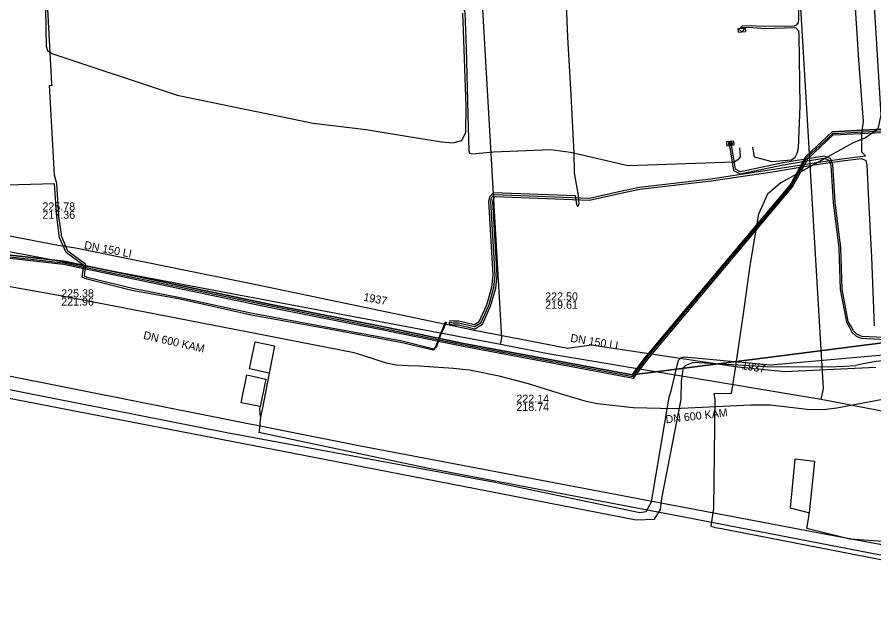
# Model space of a CAD drawing. Extents: x -599951 to -598963, y -1164095 to -1162939.
# Drawn here: x -599368.2 to -599282.6, y -1163169.1 to -1163110 of the extents above; entities that cross this region are included whole.
import ezdxf

# ---------------------------------------------------------------- set-up
doc = ezdxf.new("R2010")
doc.units = 0
for name, color, linetype in [('28', 7, 'Continuous'), ('31', 7, 'Continuous'), ('Vrstva 12', 7, 'Continuous'), ('Vrstva 13', 7, 'Continuous'), ('Vrstva 15', 7, 'Continuous'), ('Vrstva 19', 7, 'Continuous'), ('Vrstva 32', 7, 'Continuous'), ('Vrstva 42', 7, 'Continuous'), ('Vrstva 43', 7, 'Continuous'), ('Vrstva 44', 7, 'Continuous'), ('Vrstva 55', 7, 'Continuous'), ('Vrstva 58', 7, 'Continuous')]:
    doc.layers.add(name, color=color, linetype=linetype)

# ---------------------------------------------------------------- blocks, each defined once
blk = doc.blocks.new('NN630')
at = {"layer": '31'}
for points in [[(-0.003, -0.7), (-0.703, 0)], [(-0.703, -0.7), (-0.703, 0), (0.697, 0), (0.697, -0.7)], [(-0.003, -0.7), (0.697, 0)], [(-0.703, -0.7), (0.697, -0.7)]]:
    blk.add_lwpolyline(points, dxfattribs=at)
blk = doc.blocks.new('NN620')
at = {"layer": '28'}
for points in [[(0.752, 0.004), (-0.748, 0.004)], [(-0.748, 0.004), (-0.748, -0.746)], [(0.752, -0.746), (0.752, 0.004)], [(-0.748, -0.746), (0.752, -0.746)], [(0.368, -0.18), (-0.376, -0.18)], [(-0.376, -0.18), (-0.376, -0.558)], [(-0.376, -0.558), (0.368, -0.558)], [(0.321, -0.227), (-0.329, -0.227)], [(-0.329, -0.227), (-0.329, -0.51)], [(-0.329, -0.51), (0.321, -0.51)], [(0.274, -0.274), (-0.281, -0.274)], [(-0.281, -0.274), (-0.281, -0.463)], [(-0.281, -0.463), (0.274, -0.463)], [(0.227, -0.321), (-0.234, -0.321)], [(-0.234, -0.321), (-0.234, -0.416)], [(-0.234, -0.416), (0.227, -0.416)], [(-0.193, -0.369), (0.185, -0.369)], [(0.227, -0.416), (0.227, -0.321)], [(0.274, -0.463), (0.274, -0.274)], [(0.321, -0.51), (0.321, -0.227)], [(0.368, -0.558), (0.368, -0.18)]]:
    blk.add_lwpolyline(points, dxfattribs=at)

msp = doc.modelspace()

# ---------------------------------------------------------------- linework, layer by layer
at = {"layer": 'Vrstva 13'}
for p, q in [((-599370.101, -1163133.236), (-599319.892, -1163142.727)), ((-599319.892, -1163142.727), (-599319.824, -1163142.407)), ((-599287.815, -1163148.211), (-599287.66, -1163147.47)), ((-599287.815, -1163148.211), (-599286.249, -1163148.514)), ((-599286.249, -1163148.514), (-599280.123, -1163149.708))]:
    msp.add_line(p, q, dxfattribs=at)
for points in [[(-599287.66, -1163147.47), (-599287.596, -1163147.153), (-599291.469, -1163082.154), (-599292.48, -1163063.001), (-599295.243, -1163012.163), (-599300.148, -1162987.801), (-599300.278, -1162987.115), (-599302.071, -1162951.135)], [(-599319.824, -1163142.407), (-599319.759, -1163142.094), (-599323.979, -1163068.87), (-599326.68, -1163013.53)], [(-599319.892, -1163142.727), (-599314.969, -1163143.684), (-599287.815, -1163148.211)]]:
    msp.add_lwpolyline(points, dxfattribs=at)
at = {"layer": 'Vrstva 19'}
msp.add_lwpolyline([(-599283.03, -1163098.11), (-599283, -1163099.78), (-599282.98, -1163100.28), (-599282.759, -1163104.88), (-599282.75, -1163105.07), (-599281.86, -1163119.78), (-599282.17, -1163121.21), (-599283.38, -1163122.06), (-599284.63, -1163122.58), (-599291.87, -1163126.57), (-599293.2, -1163127.71), (-599294.09, -1163129.72), (-599294.97, -1163134.86), (-599295.61, -1163139.68), (-599296.53, -1163145.79), (-599296.83, -1163147.64), (-599298.55, -1163147.69), (-599298.47, -1163148.23), (-599298.58, -1163159.15), (-599298.84, -1163160.93), (-599298.41, -1163161.06), (-599297.782, -1163161.141), (-599257.68, -1163168.97), (-599257.189, -1163169.066)], dxfattribs=at)
at = {"layer": 'Vrstva 32'}
msp.add_lwpolyline([(-599248.51, -1163165.23), (-599248.91, -1163168.93), (-599262.99, -1163166.23), (-599275.57, -1163163.89), (-599281.12, -1163162.48), (-599284.95, -1163162.23), (-599289.25, -1163161.14), (-599288.98, -1163159.59), (-599288.46, -1163154.45), (-599290.46, -1163154.22), (-599290.93, -1163159.09), (-599288.98, -1163159.59)], dxfattribs=at)
at = {"layer": 'Vrstva 42'}
for p, q in [((-599372.13, -1163131.294), (-599364.125, -1163132.808)), ((-599372.13, -1163131.294), (-599364.125, -1163132.808)), ((-599364.125, -1163132.808), (-599362.379, -1163133.088)), ((-599364.125, -1163132.808), (-599362.379, -1163133.088)), ((-599362.379, -1163133.088), (-599344.332, -1163136.75)), ((-599362.379, -1163133.088), (-599344.332, -1163136.75)), ((-599344.332, -1163136.75), (-599322.486, -1163141.32)), ((-599344.332, -1163136.75), (-599322.486, -1163141.32)), ((-599322.486, -1163141.32), (-599313.151, -1163143.102)), ((-599322.486, -1163141.32), (-599313.151, -1163143.102)), ((-599313.151, -1163143.102), (-599310.811, -1163142.786)), ((-599313.151, -1163143.102), (-599310.811, -1163142.786)), ((-599310.811, -1163142.786), (-599296.158, -1163144.965)), ((-599310.811, -1163142.786), (-599296.158, -1163144.965)), ((-599296.158, -1163144.965), (-599291.448, -1163145.455)), ((-599296.158, -1163144.965), (-599291.448, -1163145.455)), ((-599291.448, -1163145.455), (-599282.345, -1163145.018)), ((-599291.448, -1163145.455), (-599282.345, -1163145.018))]:
    msp.add_line(p, q, dxfattribs=at)
for points in [[(-599294.695, -1163123.004), (-599294.507, -1163123.992), (-599292.74, -1163124.44), (-599290.8, -1163124.28), (-599290.43, -1163124.02), (-599290.23, -1163123.6), (-599290.09, -1163123.11), (-599289.92, -1163118.87), (-599290.02, -1163111.8), (-599290.06, -1163111.4), (-599290.31, -1163111.12), (-599290.52, -1163111.06), (-599293.44, -1163111.16), (-599295.055, -1163111.045), (-599295.64, -1163111.069), (-599295.759, -1163111.123), (-599295.83, -1163111.038), (-599295.802, -1163110.949), (-599295.758, -1163110.89), (-599295.672, -1163110.87), (-599295.063, -1163110.845), (-599293.49, -1163110.9), (-599290.52, -1163110.86), (-599290.27, -1163110.77), (-599290.1, -1163110.53), (-599290.04, -1163110.17), (-599290.09, -1163105.95)], [(-599365.4, -1163107.45), (-599365.303, -1163112.901), (-599365.168, -1163113.345), (-599364.746, -1163113.648), (-599352.22, -1163117.82), (-599338.62, -1163120.62), (-599333.33, -1163121.25), (-599329.48, -1163121.89), (-599325.78, -1163122.49), (-599324.667, -1163122.575), (-599323.749, -1163122.355), (-599323.345, -1163121.51), (-599323.329, -1163118.949), (-599323.53, -1163113.2), (-599323.64, -1163109.59)], [(-599295.997, -1163123.089), (-599295.935, -1163123.981), (-599296.145, -1163124.281), (-599296.534, -1163124.502), (-599307.11, -1163124.86), (-599312.87, -1163123.53), (-599314.9, -1163123.29), (-599320.59, -1163123.51), (-599322.73, -1163123.72), (-599322.95, -1163123.64), (-599323.02, -1163123.4), (-599323.108, -1163119.753), (-599323.27, -1163113.13), (-599323.42, -1163109.54), (-599323.915, -1163107.93), (-599324.309, -1163107.715), (-599324.718, -1163107.606), (-599327.531, -1163107.6), (-599335.893, -1163108.249)], [(-599281.779, -1163121.225), (-599286.734, -1163121.489), (-599289.36, -1163123.957), (-599290.924, -1163126.795), (-599305.397, -1163144.027), (-599306.724, -1163145.785), (-599323.571, -1163142.633), (-599331.22, -1163141.053), (-599342.82, -1163138.743), (-599363.546, -1163134.422), (-599373.957, -1163133.252), (-599387.743, -1163130.523), (-599399.57, -1163128.413), (-599413.855, -1163125.204), (-599424.959, -1163122.443), (-599440.16, -1163119.773), (-599450.931, -1163117.323), (-599460.553, -1163115.713)], [(-599281.779, -1163121.225), (-599286.734, -1163121.489), (-599289.36, -1163123.957), (-599290.924, -1163126.795), (-599305.397, -1163144.027), (-599306.724, -1163145.785), (-599323.571, -1163142.633), (-599331.22, -1163141.053), (-599342.82, -1163138.743), (-599363.546, -1163134.422), (-599373.957, -1163133.252), (-599387.743, -1163130.523), (-599399.57, -1163128.413), (-599413.855, -1163125.204), (-599424.959, -1163122.443), (-599440.16, -1163119.773), (-599450.931, -1163117.323), (-599460.553, -1163115.713)], [(-599460.553, -1163115.713), (-599450.931, -1163117.323), (-599440.16, -1163119.773), (-599424.959, -1163122.443), (-599413.855, -1163125.204), (-599399.57, -1163128.413), (-599387.743, -1163130.523), (-599373.957, -1163133.252), (-599363.546, -1163134.422), (-599342.82, -1163138.743), (-599331.22, -1163141.053), (-599323.571, -1163142.633), (-599306.724, -1163145.785), (-599305.397, -1163144.027), (-599290.924, -1163126.795), (-599289.36, -1163123.957), (-599286.734, -1163121.489), (-599281.779, -1163121.225)], [(-599460.553, -1163115.713), (-599450.931, -1163117.323), (-599440.16, -1163119.773), (-599424.959, -1163122.443), (-599413.855, -1163125.204), (-599399.57, -1163128.413), (-599387.743, -1163130.523), (-599373.957, -1163133.252), (-599363.546, -1163134.422), (-599342.82, -1163138.743), (-599331.22, -1163141.053), (-599323.571, -1163142.633), (-599306.724, -1163145.785), (-599305.397, -1163144.027), (-599290.924, -1163126.795), (-599289.36, -1163123.957), (-599286.734, -1163121.489), (-599281.779, -1163121.225)], [(-599460.607, -1163116.007), (-599450.989, -1163117.617), (-599440.22, -1163120.067), (-599425.021, -1163122.737), (-599413.925, -1163125.496), (-599399.63, -1163128.707), (-599387.797, -1163130.817), (-599374.003, -1163133.548), (-599363.594, -1163134.718), (-599342.88, -1163139.037), (-599331.28, -1163141.347), (-599323.629, -1163142.927), (-599306.596, -1163146.115), (-599305.163, -1163144.213), (-599290.676, -1163126.965), (-599289.12, -1163124.143), (-599286.609, -1163121.783), (-599281.778, -1163121.526)], [(-599460.607, -1163116.007), (-599450.989, -1163117.617), (-599440.22, -1163120.067), (-599425.021, -1163122.737), (-599413.925, -1163125.496), (-599399.63, -1163128.707), (-599387.797, -1163130.817), (-599374.003, -1163133.548), (-599363.594, -1163134.718), (-599342.88, -1163139.037), (-599331.28, -1163141.347), (-599323.629, -1163142.927), (-599306.596, -1163146.115), (-599305.163, -1163144.213), (-599290.676, -1163126.965), (-599289.12, -1163124.143), (-599286.609, -1163121.783), (-599281.778, -1163121.526)], [(-599460.581, -1163115.86), (-599450.96, -1163117.47), (-599440.19, -1163119.92), (-599424.99, -1163122.59), (-599413.89, -1163125.35), (-599399.6, -1163128.56), (-599387.771, -1163130.67), (-599373.98, -1163133.4), (-599363.57, -1163134.57), (-599342.85, -1163138.89), (-599331.25, -1163141.2), (-599323.6, -1163142.78), (-599306.66, -1163145.95), (-599305.28, -1163144.12), (-599290.8, -1163126.88), (-599289.24, -1163124.05), (-599286.671, -1163121.636), (-599281.778, -1163121.375)], [(-599296.979, -1163122.836), (-599296.571, -1163125.334), (-599295.936, -1163125.686), (-599291.622, -1163124.768), (-599287.54, -1163124.123), (-599287.057, -1163124.298), (-599286.869, -1163124.801), (-599286.62, -1163128.53), (-599286.05, -1163133.098), (-599285.92, -1163137.251), (-599285.305, -1163140.525), (-599284.998, -1163141.058), (-599284.76, -1163141.512), (-599284.325, -1163141.905), (-599283.813, -1163142.129), (-599280.114, -1163142.31)], [(-599280.106, -1163142.11), (-599283.767, -1163141.931), (-599284.215, -1163141.735), (-599284.6, -1163141.388), (-599284.822, -1163140.962), (-599285.115, -1163140.455), (-599285.72, -1163137.229), (-599285.85, -1163133.082), (-599286.42, -1163128.51), (-599286.671, -1163124.759), (-599286.903, -1163124.142), (-599287.52, -1163123.917), (-599291.658, -1163124.572), (-599295.904, -1163125.474), (-599296.389, -1163125.206), (-599296.781, -1163122.804)], [(-599281.84, -1163148.27), (-599286.24, -1163149.13), (-599287.63, -1163149.28), (-599289.23, -1163149.24), (-599292.88, -1163148.81), (-599294.86, -1163148.82), (-599302.51, -1163149.17), (-599306.62, -1163149.08), (-599310.18, -1163148.68), (-599311.31, -1163148.46), (-599314.22, -1163147.57), (-599317.07, -1163146.67), (-599320.01, -1163145.9), (-599322.99, -1163145.33), (-599324.61, -1163145.14), (-599327.99, -1163144.91), (-599329.09, -1163144.89), (-599330.31, -1163144.81), (-599331.3, -1163144.6), (-599333.64, -1163143.85), (-599334.52, -1163143.59), (-599345.12, -1163141.51), (-599355.57, -1163139.49), (-599363.89, -1163137.89), (-599373.63, -1163136.13)], [(-599252.181, -1163138.924), (-599257.96, -1163139.537), (-599306.724, -1163145.785)], [(-599306.724, -1163145.785), (-599257.96, -1163139.537), (-599252.181, -1163138.924)], [(-599343.01, -1163145.628), (-599344.976, -1163145.198), (-599344.407, -1163142.496), (-599342.485, -1163142.885), (-599343.01, -1163145.628), (-599343.717, -1163149.265), (-599343.892, -1163149.968), (-599344.03, -1163151.373), (-599344.06, -1163151.57)], [(-599343.892, -1163149.968), (-599343.96, -1163149.222), (-599343.909, -1163148.956), (-599345.824, -1163148.567), (-599345.242, -1163145.795), (-599343.341, -1163146.201), (-599343.909, -1163148.956)], [(-599249.066, -1163166.057), (-599249.356, -1163168.677), (-599255.971, -1163167.763), (-599257.128, -1163168.196), (-599257.477, -1163168.103), (-599274.919, -1163165.108), (-599278.939, -1163164.385), (-599301.203, -1163160.101), (-599327.234, -1163155.124), (-599344.064, -1163151.566)]]:
    msp.add_lwpolyline(points, dxfattribs=at)
at = {"layer": 'Vrstva 44'}
for points in [[(-599475.32, -1163127.533), (-599436.546, -1163134.88), (-599411.698, -1163139.793), (-599397.5, -1163142.504), (-599370.257, -1163147.895), (-599338.502, -1163154.014), (-599306.306, -1163160.272), (-599304.481, -1163160.215), (-599303.886, -1163159.262), (-599303.749, -1163158.164), (-599301.826, -1163148.263), (-599301.773, -1163146.426), (-599301.583, -1163145.05), (-599301.347, -1163144.827), (-599300.578, -1163144.512), (-599293.352, -1163144.936), (-599287.117, -1163144.97), (-599285.472, -1163144.911), (-599284.37, -1163144.858)], [(-599263.428, -1163137.585), (-599264.177, -1163138.062), (-599273.629, -1163143.656), (-599282.37, -1163144.448), (-599283.611, -1163144.674), (-599284.37, -1163144.858)]]:
    msp.add_lwpolyline(points, dxfattribs=at)
at = {"layer": 'Vrstva 55'}
for points in [[(-599618.855, -1163097.599), (-599597.44, -1163101.87), (-599562.87, -1163108.53), (-599528.51, -1163115.32), (-599493.94, -1163122.04), (-599459.65, -1163128.7), (-599425.29, -1163135.35), (-599390.79, -1163142.01), (-599379.04, -1163144.18), (-599370.08, -1163145.68), (-599333.88, -1163152.87), (-599287.5, -1163161.7), (-599253.07, -1163168.09), (-599247.97, -1163169.04), (-599246.945, -1163169.092), (-599247.03, -1163167.178), (-599245.243, -1163166.795)], [(-599325.373, -1163140.487), (-599325.96, -1163141.82), (-599326.36, -1163142.92), (-599326.56, -1163143.2), (-599329.73, -1163142.41), (-599337.35, -1163141.01), (-599344.86, -1163139.61), (-599351.91, -1163138.08), (-599356.7, -1163137.15), (-599361.2, -1163136.05), (-599361.493, -1163135.9), (-599361.343, -1163134.745), (-599363.14, -1163133.415), (-599363.755, -1163131.991), (-599364.039, -1163129.945), (-599364.264, -1163126.632), (-599364.49, -1163125.82), (-599364.98, -1163116.81), (-599364.72, -1163116.84), (-599364.74, -1163116.68), (-599365.35, -1163105.4)], [(-599325.031, -1163140.496), (-599324.636, -1163140.59), (-599324.07, -1163140.59), (-599322.49, -1163140.96), (-599321.85, -1163140.58), (-599321.06, -1163138.86), (-599320.56, -1163137.06), (-599320.41, -1163135.8), (-599320.85, -1163128.44), (-599320.74, -1163128.01), (-599320.49, -1163127.75), (-599310.98, -1163128.1), (-599308.07, -1163127.452), (-599305.986, -1163127.011), (-599298.853, -1163126.171), (-599289.566, -1163124.731), (-599288.335, -1163124.531), (-599285.765, -1163124.191), (-599283.38, -1163123.89), (-599283.75, -1163123.52), (-599283.75, -1163121.57), (-599283.6, -1163120.44), (-599284.05, -1163114.26), (-599284.45, -1163108.02)], [(-599324.997, -1163140.36), (-599324.597, -1163140.39), (-599324.047, -1163140.39), (-599322.523, -1163140.747), (-599322.006, -1163140.44), (-599321.248, -1163138.791), (-599320.757, -1163137.021), (-599320.611, -1163135.794), (-599321.052, -1163128.421), (-599320.921, -1163127.909), (-599320.572, -1163127.547), (-599312.418, -1163127.847), (-599312.281, -1163128.732), (-599312.16, -1163128.96), (-599312.032, -1163128.646), (-599312.093, -1163127.839), (-599312.47, -1163125.59), (-599312.53, -1163123.62), (-599312.82, -1163117.8), (-599313.15, -1163112.01), (-599313.28, -1163108.73)], [(-599325.077, -1163140.558), (-599324.946, -1163140.718), (-599324.634, -1163140.794), (-599324.093, -1163140.79), (-599322.457, -1163141.173), (-599321.694, -1163140.72), (-599320.872, -1163138.929), (-599320.363, -1163137.099), (-599320.209, -1163135.806), (-599320.648, -1163128.459), (-599320.559, -1163128.111), (-599320.408, -1163127.953), (-599310.987, -1163128.3), (-599308.03, -1163127.648), (-599305.954, -1163127.209), (-599298.827, -1163126.369), (-599292.684, -1163125.469), (-599289.534, -1163124.929), (-599288.305, -1163124.729), (-599285.735, -1163124.389), (-599283.791, -1163124.151), (-599283.363, -1163124.345), (-599283.27, -1163124.78), (-599283.08, -1163128.31), (-599282.79, -1163134), (-599282.52, -1163140.87)], [(-599325.274, -1163140.504), (-599325.904, -1163141.866), (-599326.29, -1163142.97), (-599326.57, -1163143.3), (-599329.72, -1163142.57), (-599337.38, -1163141.15), (-599344.83, -1163139.81), (-599351.92, -1163138.21), (-599356.75, -1163137.33), (-599361.26, -1163136.21), (-599361.707, -1163136), (-599361.557, -1163134.835), (-599363.3, -1163133.545), (-599363.967, -1163132.078), (-599364.26, -1163129.98), (-599364.47, -1163126.67), (-599370.47, -1163126.84)]]:
    msp.add_lwpolyline(points, dxfattribs=at)
at = {"layer": 'Vrstva 58'}
msp.add_lwpolyline([(-599467.296, -1163128.595), (-599449.626, -1163131.895), (-599436.436, -1163134.445), (-599424.726, -1163136.395), (-599396.496, -1163142.065), (-599373.566, -1163146.345), (-599347.266, -1163151.545), (-599320.246, -1163156.535), (-599305.966, -1163159.545), (-599305.336, -1163159.455), (-599304.796, -1163158.485), (-599303.026, -1163148.025), (-599302.836, -1163147.375), (-599302.096, -1163144.325), (-599301.866, -1163144.085), (-599301.526, -1163143.995), (-599292.886, -1163144.775), (-599281.976, -1163143.815), (-599273.586, -1163142.935), (-599269.986, -1163140.635), (-599256.936, -1163131.305), (-599250.816, -1163125.405)], dxfattribs=at)
msp.add_lwpolyline([(-599467.296, -1163128.595), (-599449.626, -1163131.895), (-599436.436, -1163134.445), (-599424.726, -1163136.395), (-599396.496, -1163142.065), (-599373.566, -1163146.345), (-599347.266, -1163151.545), (-599320.246, -1163156.535), (-599305.966, -1163159.545), (-599305.336, -1163159.455), (-599304.796, -1163158.485), (-599303.026, -1163148.025), (-599302.836, -1163147.375), (-599302.096, -1163144.325), (-599301.866, -1163144.085), (-599301.526, -1163143.995), (-599292.886, -1163144.775), (-599281.976, -1163143.815), (-599273.586, -1163142.935), (-599269.986, -1163140.635), (-599256.936, -1163131.305), (-599250.816, -1163125.405)], dxfattribs=at)

# ---------------------------------------------------------------- block references
at = {"layer": 'Vrstva 43'}
for name, p, xscale, yscale, rotation in [('NN630', (-599295.759, -1163111.123), 0.5000000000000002, 0.4999999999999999, 3.0000000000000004), ('NN620', (-599296.88, -1163122.82), 0.5, 0.5000000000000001, -174.00000000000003)]:
    msp.add_blockref(name, p, dxfattribs=dict(at, xscale=xscale, yscale=yscale, rotation=rotation))

# ---------------------------------------------------------------- texts
at = {"layer": 'Vrstva 12'}
for s, p in [('225.78', (-599365.692, -1163129.338)), ('217.36', (-599365.692, -1163130.17)), ('225.38', (-599363.814, -1163138.028)), ('221.96', (-599363.814, -1163138.86)), ('222.50', (-599315.417, -1163138.342)), ('219.61', (-599315.417, -1163139.174)), ('222.14', (-599318.299, -1163148.569)), ('218.74', (-599318.299, -1163149.401))]:
    msp.add_text(s, height=0.8, dxfattribs=at).set_placement(p)
for rotation, p in [(346.97152, (-599355.66, -1163142.171)), (6.58901, (-599303.336, -1163150.64))]:
    msp.add_text('DN 600 KAM', height=0.8, rotation=rotation, dxfattribs=at).set_placement(p)
at = {"layer": 'Vrstva 15'}
for s, rotation, p in [('DN 150 LI', 349.27507, (-599361.569, -1163133.168)), ('1937', 349.27507, (-599333.641, -1163138.36)), ('DN 150 LI', 350.53558, (-599312.939, -1163142.465)), ('1937', 350.53558, (-599295.809, -1163145.202))]:
    msp.add_text(s, height=0.8, rotation=rotation, dxfattribs=at).set_placement(p)

doc.saveas('drawing.dxf')
